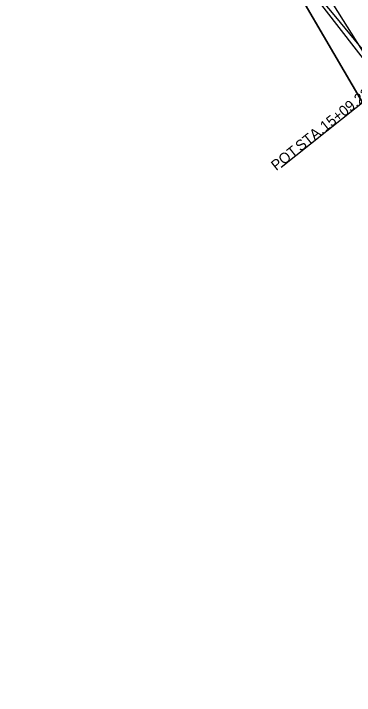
# Model space of a CAD drawing. Extents: x 208278 to 2196496, y 417130 to 637870.
# Drawn here: x 208609.1 to 208699.6, y 418508.4 to 418689.3 of the extents above; entities that cross this region are included whole.
import ezdxf

# ---------------------------------------------------------------- set-up
doc = ezdxf.new("R2010")
doc.units = 0
for name, color, linetype in [('BR_P_Beam', 7, 'Continuous'), ('PM_P_Edge_Line', 7, 'Continuous'), ('RD_P_Concrete_Barrier', 7, 'Continuous'), ('RD_P_Gate', 7, 'Continuous'), ('UT_P_Sanitary', 7, 'Continuous')]:
    doc.layers.add(name, color=color, linetype=linetype)

msp = doc.modelspace()

# ---------------------------------------------------------------- linework, layer by layer
at = {"layer": 'BR_P_Beam'}
msp.add_lwpolyline([(208688, 418718.64), (208723.16, 418682.73), (208707.52, 418670.26), (208676.92, 418709.81)], dxfattribs=at)
at = {"layer": 'PM_P_Edge_Line'}
msp.add_lwpolyline([(208907.35, 418482.67), (208831.39, 418569.35), (208820.48, 418604.66), (208825.24, 418627.24), (208843.38, 418643.29), (208801.29, 418679.21), (208789.33, 418672.19), (208764.16, 418694.07), (208750.91, 418706.21), (208726.61, 418685.4), (208688.67, 418719.37), (208676.21, 418709.55), (208701.79, 418665.69), (208711.96, 418632.05), (208718.89, 418619.57), (208728.74, 418605.78), (208726.97, 418600.31), (208739.74, 418591.32), (208756.31, 418580.12), (208764.39, 418572.04), (208817.72, 418512.04), (208850.32, 418472.01)], dxfattribs=at)
at = {"layer": 'RD_P_Concrete_Barrier'}
for points, degree in [([(208609.05, 418791.74), (208754.84, 418615.78), (208765.24, 418602.84), (208786.46, 418576.01), (208805.09, 418552.36), (208822.06, 418531.18), (208839.68, 418510.58), (208850.53, 418496.21), (208868.33, 418473.16), (208885.98, 418449.74), (208901.76, 418429.46), (208923.53, 418401.55), (208946.91, 418370.95), (208973.19, 418337.11), (208998.37, 418302.71), (209011.82, 418283.75), (209029.87, 418257.68), (209043.7, 418235.61), (209066.13, 418198.05), (209073.85, 418182.85), (209084.25, 418161.82), (209095.54, 418134.5), (209105.49, 418106.74), (209112.75, 418083.23), (209118.4, 418061.3), (209125.65, 418028.96), (209131.8, 418004.65), (209135.32, 417980.96), (209140.18, 417952.97), (209143.43, 417932.17), (209146.71, 417910.42), (209149.06, 417894.12), (209152.03, 417869.62), (209153.49, 417849.93), (209154.1, 417829.36), (209154.52, 417812.83), (209153.97, 417793.32), (209152.56, 417777.57), (209149.95, 417760.2), (209147.7, 417748.06), (209143.21, 417727.93), (209137.45, 417707.72), (209132.12, 417689.59), (209126.06, 417672.9), (209115.97, 417648.15), (209109.02, 417628.62), (209106.47, 417617.02), (209104.98, 417608.71), (209104.45, 417598.01), (209104.31, 417580.42), (209105.49, 417557.54), (209107.29, 417538.08), (209110.88, 417513.39), (209122.57, 417470.17), (209132.91, 417432.97), (209150.06, 417393.82), (209161.49, 417373.71), (209168.97, 417360.7), (209172.4, 417352.45), (209174.02, 417344.77), (209169.23, 417333.02), (209154.07, 417324.14)], 2), ([(208642.14, 418773.81), (208766.73, 418623.92), (208771.32, 418618.43), (208777.59, 418619.21), (208781.59, 418621), (208784.17, 418623.87)], 3)]:
    msp.add_open_spline(points, degree=degree, dxfattribs=at)
at = {"layer": 'RD_P_Gate'}
for points in [[(208850.32, 418472.01), (208817.72, 418512.04), (208764.39, 418572.04), (208756.31, 418580.12), (208739.74, 418591.32), (208726.97, 418600.31), (208728.74, 418605.78), (208718.89, 418619.57), (208711.96, 418632.05), (208701.79, 418665.69), (208676.21, 418709.55), (208688.67, 418719.37), (208726.61, 418685.4), (208750.91, 418706.21), (208764.16, 418694.07), (208789.33, 418672.19), (208801.29, 418679.21), (208843.38, 418643.29), (208825.24, 418627.24), (208820.48, 418604.66), (208836.36, 418563.68), (208910.4, 418478.58)], [(208723.16, 418682.73), (208690.36, 418712.33), (208684.25, 418707.24), (208707.52, 418670.26)], [(208743.13, 418657.67), (208723.16, 418682.73), (208690.36, 418712.33), (208684.25, 418707.24), (208707.52, 418670.26), (208836.57, 418508.38)]]:
    msp.add_lwpolyline(points, dxfattribs=at)
at = {"layer": 'UT_P_Sanitary'}
msp.add_line((208715.34, 418676.49), (208680.15, 418648.44), dxfattribs=at)

# ---------------------------------------------------------------- texts
for s, p in [('15+09.23', (208691.89, 418657.85)), (' STA. ', (208684.5, 418651.96)), ('POT', (208678.87, 418647.47))]:
    msp.add_text(s, height=2.8, rotation=38.5618, dxfattribs=at).set_placement(p)

doc.saveas('drawing.dxf')
